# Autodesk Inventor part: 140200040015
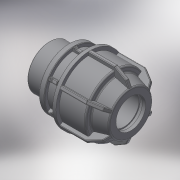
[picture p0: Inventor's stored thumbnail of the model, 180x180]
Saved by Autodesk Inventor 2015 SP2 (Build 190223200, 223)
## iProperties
Created: 2017-08
Part Number: 140200040015
Material: Generic
Description: PLASSON L.14 MALE ADAPTOR (SILVER) 40-1.1/2''
Document SubType Name: Modeling
Designer: KIM
Density: 1 g/cm^3
Appearance: Default
Author: KIM
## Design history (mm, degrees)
derived "140200.ipt"
feature "Solid1::140200.ipt"
tag "TaggingFeature1"
body "Solid1"
other parameters: "d2" = 73, "d4" = 15 deg, "d5" = 48.18, "d6" = 15.8994, "d10" = 73, "d16" = 40.8, "d17" = 3.65, "d18" = 98, "d19" = 6.6, "d21" = 6.6, "d22" = 57.3636, "d24" = 3.65, "d25" = 65.7, "d26" = 54.75, "d27" = 3.65, "d28" = 135 deg, "d29" = 2.19, "d31" = 2, "d44" = 0.8, "d45" = 1.2, "d46" = 150 deg, "d49" = 3.65, "d50" = 0, "d51" = 2.19, "d52" = 1.46, "d53" = 45 deg, "d54" = 21, "d55" = 6.3, "d56" = 3.65, "d57" = 0, "d58" = 1.2, "d59" = 0.8, "d61" = 360 deg, "d63" = 47.803, "d64" = 32, "d65" = 22, "d66" = 64.53405, "R_" = 47.803, "E_" = 73, "H_" = 98, "l_" = 73, "l_2" = 22
